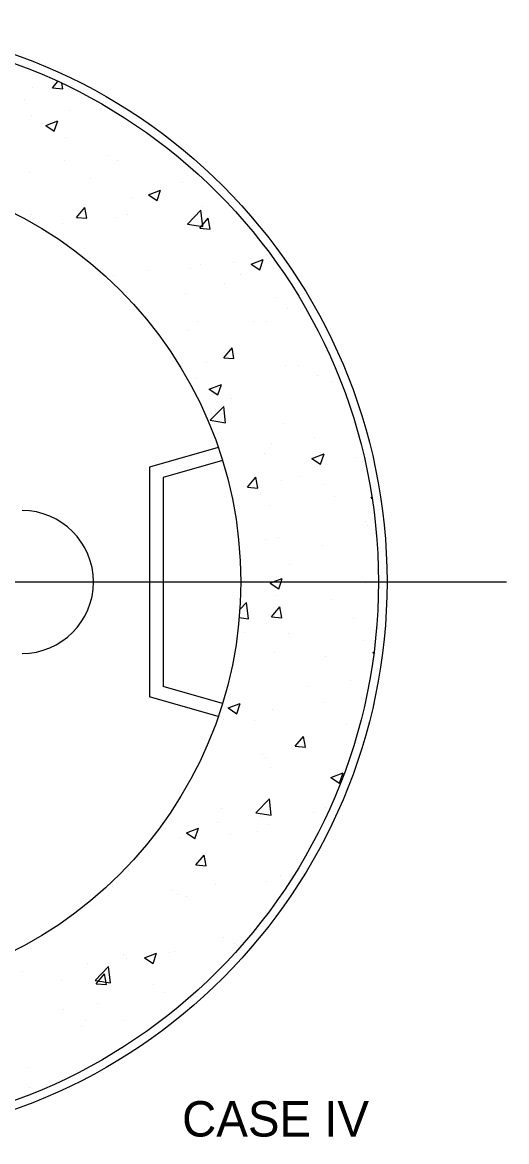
# Model space of a CAD drawing. Extents: x 6712067 to 6713867, y 1867712 to 1869162.
# Drawn here: x 6713358.3 to 6713440.3, y 1867927.4 to 1868116.9 of the extents above; entities that cross this region are included whole.
import ezdxf

# ---------------------------------------------------------------- set-up
doc = ezdxf.new("R2010")
doc.units = 0
doc.layers.add('Misc CnstDet(22)', color=7, linetype='Continuous')

msp = doc.modelspace()

# ---------------------------------------------------------------- linework, layer by layer
at = {"layer": 'Misc CnstDet(22)'}
for p, q in [((6713360.06, 1868105.89), (6713360.06, 1868105.89)), ((6713363.4, 1868105.8), (6713364.32, 1868106.89)), ((6713363.4, 1868105.8), (6713365.14, 1868105.65)), ((6713365.14, 1868105.64), (6713364.97, 1868106.58)), ((6713358.68, 1868103.8), (6713358.68, 1868103.8)), ((6713366.2, 1868101.98), (6713366.2, 1868101.98)), ((6713359.76, 1868101.15), (6713359.76, 1868101.15)), ((6713362.25, 1868099.43), (6713364.3, 1868100.22)), ((6713363.7, 1868098.45), (6713364.28, 1868100.21)), ((6713362.25, 1868099.43), (6713363.7, 1868098.45)), ((6713365.66, 1868097.41), (6713365.66, 1868097.41)), ((6713372.71, 1868094.39), (6713372.71, 1868094.39)), ((6713365.41, 1868093.43), (6713365.41, 1868093.43)), ((6713374.38, 1868093.51), (6713374.38, 1868093.51)), ((6713359.42, 1868091.45), (6713359.42, 1868091.45)), ((6713369.82, 1868090.42), (6713369.82, 1868090.42)), ((6713379.65, 1868087.7), (6713381.69, 1868088.48)), ((6713381.1, 1868086.71), (6713381.69, 1868088.48)), ((6713385.38, 1868089.75), (6713385.38, 1868089.75)), ((6713376.79, 1868087.21), (6713376.79, 1868087.21)), ((6713379.65, 1868087.7), (6713381.1, 1868086.71)), ((6713359.8, 1868084.29), (6713359.8, 1868084.29)), ((6713367.45, 1868083.87), (6713368.85, 1868085.54)), ((6713369.2, 1868083.72), (6713368.85, 1868085.54)), ((6713376.08, 1868084.35), (6713376.08, 1868084.35)), ((6713386.27, 1868082.74), (6713388.53, 1868085.11)), ((6713388.85, 1868082.33), (6713388.53, 1868085.11)), ((6713388.75, 1868085.67), (6713388.75, 1868085.67)), ((6713365.04, 1868082.89), (6713365.04, 1868082.89)), ((6713367.45, 1868083.87), (6713369.2, 1868083.72)), ((6713374.03, 1868083.8), (6713374.03, 1868083.8)), ((6713386.27, 1868082.74), (6713388.85, 1868082.34)), ((6713388.36, 1868082.04), (6713389.76, 1868083.72)), ((6713390.09, 1868081.88), (6713389.76, 1868083.72)), ((6713388.36, 1868082.04), (6713390.1, 1868081.89)), ((6713397.05, 1868075.96), (6713399.09, 1868076.74)), ((6713398.49, 1868074.98), (6713399.09, 1868076.74)), ((6713379.71, 1868074.86), (6713379.71, 1868074.86)), ((6713386.82, 1868075.27), (6713386.82, 1868075.27)), ((6713388.39, 1868075.96), (6713388.39, 1868075.96)), ((6713394.12, 1868076.24), (6713394.12, 1868076.24)), ((6713397.05, 1868075.96), (6713398.49, 1868074.98)), ((6713373.67, 1868074.1), (6713373.67, 1868074.1)), ((6713395.27, 1868074.2), (6713395.27, 1868074.2)), ((6713392.6, 1868072.74), (6713392.6, 1868072.74)), ((6713385.85, 1868070.95), (6713385.85, 1868070.95)), ((6713401.41, 1868070.29), (6713401.41, 1868070.29)), ((6713403.18, 1868068.44), (6713403.18, 1868068.44)), ((6713388.04, 1868066.26), (6713388.04, 1868066.26)), ((6713397.5, 1868066.18), (6713397.5, 1868066.18)), ((6713399.57, 1868066.33), (6713399.57, 1868066.33)), ((6713386.46, 1868064.74), (6713386.46, 1868064.74)), ((6713382.58, 1868063.42), (6713382.58, 1868063.42)), ((6713392.4, 1868060.11), (6713393.81, 1868061.79)), ((6713394.14, 1868059.96), (6713393.81, 1868061.79)), ((6713392.4, 1868060.11), (6713394.14, 1868059.96)), ((6713389.46, 1868059.39), (6713389.46, 1868059.39)), ((6713402.82, 1868058.75), (6713402.82, 1868058.75)), ((6713405.02, 1868058.73), (6713405.02, 1868058.73)), ((6713387.68, 1868056.55), (6713387.68, 1868056.55)), ((6713408.24, 1868057.12), (6713408.24, 1868057.12)), ((6713410.7, 1868056.13), (6713410.7, 1868056.13)), ((6713389.82, 1868054.7), (6713389.82, 1868054.7)), ((6713389.96, 1868054.82), (6713392, 1868055.6)), ((6713389.96, 1868054.82), (6713391.4, 1868053.85)), ((6713391.4, 1868053.85), (6713392, 1868055.6)), ((6713393.71, 1868053.21), (6713393.71, 1868053.21)), ((6713390.13, 1868049.52), (6713392.4, 1868051.88)), ((6713392.72, 1868049.12), (6713392.4, 1868051.88)), ((6713390.13, 1868049.52), (6713392.72, 1868049.12)), ((6713402.48, 1868049.04), (6713402.48, 1868049.04)), ((6713407.86, 1868046.58), (6713407.86, 1868046.58)), ((6713391.47, 1868044.93), (6713379.83, 1868041.6)), ((6713400.56, 1868045.62), (6713400.56, 1868045.62)), ((6713392.19, 1868042.71), (6713382.17, 1868039.85)), ((6713399.35, 1868043.84), (6713399.35, 1868043.84)), ((6713407.35, 1868043.08), (6713409.4, 1868043.87)), ((6713407.35, 1868043.08), (6713408.8, 1868042.11)), ((6713408.8, 1868042.11), (6713409.4, 1868043.86)), ((6713414.92, 1868043.17), (6713414.92, 1868043.17)), ((6713379.83, 1868041.6), (6713379.83, 1868002.69)), ((6713382.17, 1868039.85), (6713382.17, 1868004.45)), ((6713396.45, 1868038.19), (6713397.85, 1868039.87)), ((6713398.18, 1868038.03), (6713397.85, 1868039.87)), ((6713402.12, 1868039.34), (6713402.12, 1868039.34)), ((6713405.49, 1868039.93), (6713405.49, 1868039.93)), ((6713396.45, 1868038.19), (6713398.18, 1868038.04)), ((6713409.5, 1868038.73), (6713409.5, 1868038.73)), ((6713400.19, 1868035.08), (6713400.19, 1868035.08)), ((6713411.23, 1868036.54), (6713411.23, 1868036.54)), ((6713417.35, 1868036.36), (6713417.49, 1868036.53)), ((6713417.35, 1868036.36), (6713417.52, 1868036.35)), ((6713416.49, 1868032.34), (6713416.49, 1868032.34)), ((6713416.73, 1868031.69), (6713416.73, 1868031.69)), ((6713399.49, 1868029.41), (6713399.49, 1868029.41)), ((6713401.76, 1868029.63), (6713401.76, 1868029.63)), ((6713409.11, 1868028.36), (6713409.11, 1868028.36)), ((6713403.57, 1868025.04), (6713403.57, 1868025.04)), ((6713210.33, 1868022.15), (6713440.32, 1868022.15)), ((6713400.26, 1868021.95), (6713400.78, 1868022.15)), ((6713400.26, 1868021.95), (6713401.71, 1868020.97)), ((6713400.78, 1868022.15), (6713402.3, 1868022.73)), ((6713401.71, 1868020.97), (6713402.11, 1868022.15)), ((6713402.11, 1868022.15), (6713402.3, 1868022.73)), ((6713416.37, 1868021.98), (6713416.37, 1868021.98)), ((6713401.41, 1868019.92), (6713401.41, 1868019.92)), ((6713395.13, 1868017.48), (6713396.27, 1868018.66)), ((6713396.59, 1868015.89), (6713396.27, 1868018.66)), ((6713410.62, 1868019.22), (6713410.62, 1868019.22)), ((6713395.03, 1868016.14), (6713396.59, 1868015.89)), ((6713400.49, 1868016.26), (6713401.89, 1868017.94)), ((6713400.49, 1868016.26), (6713402.23, 1868016.11)), ((6713402.23, 1868016.11), (6713401.89, 1868017.94)), ((6713414.31, 1868015.96), (6713414.31, 1868015.96)), ((6713395.9, 1868013.54), (6713395.9, 1868013.54)), ((6713403.44, 1868013.46), (6713403.44, 1868013.46)), ((6713416.02, 1868012.28), (6713416.02, 1868012.28)), ((6713401.05, 1868010.23), (6713401.05, 1868010.23)), ((6713409.58, 1868009.55), (6713409.58, 1868009.55)), ((6713417.66, 1868010.21), (6713417.85, 1868010.28)), ((6713417.66, 1868010.21), (6713417.82, 1868010.1)), ((6713413.93, 1868005.43), (6713413.93, 1868005.43)), ((6713392.19, 1868001.58), (6713382.17, 1868004.45)), ((6713406.64, 1868004.46), (6713406.64, 1868004.46)), ((6713391.47, 1867999.37), (6713379.83, 1868002.69)), ((6713393.17, 1868000.82), (6713395.21, 1868001.6)), ((6713394.61, 1867999.83), (6713395.21, 1868001.6)), ((6713409.42, 1868001.83), (6713409.42, 1868001.83)), ((6713415.66, 1868002.57), (6713415.66, 1868002.57)), ((6713393.17, 1868000.82), (6713394.61, 1867999.83)), ((6713400.7, 1868000.52), (6713400.7, 1868000.52)), ((6713392.42, 1867998.91), (6713392.42, 1867998.91)), ((6713397.63, 1867998.65), (6713397.63, 1867998.65)), ((6713413.19, 1867997.99), (6713413.19, 1867997.99)), ((6713404.53, 1867994.34), (6713405.94, 1867996.02)), ((6713406.27, 1867994.18), (6713405.94, 1867996.01)), ((6713404.53, 1867994.34), (6713406.27, 1867994.18)), ((6713406.26, 1867993.93), (6713406.26, 1867993.93)), ((6713398.96, 1867992.98), (6713398.96, 1867992.98)), ((6713399.4, 1867992.51), (6713399.4, 1867992.51)), ((6713400.34, 1867990.82), (6713400.34, 1867990.82)), ((6713410.57, 1867989.08), (6713412.61, 1867989.86)), ((6713412.01, 1867988.1), (6713412.61, 1867989.86)), ((6713410.57, 1867989.08), (6713412.02, 1867988.1)), ((6713397.86, 1867983.09), (6713400.13, 1867985.45)), ((6713400.46, 1867982.67), (6713400.13, 1867985.45)), ((6713409.64, 1867983.89), (6713409.64, 1867983.89)), ((6713391.96, 1867983.75), (6713391.96, 1867983.75)), ((6713397.86, 1867983.09), (6713400.46, 1867982.68)), ((6713398.6, 1867982.44), (6713398.6, 1867982.44)), ((6713407.53, 1867983.1), (6713407.53, 1867983.1)), ((6713382.54, 1867980.5), (6713382.54, 1867980.5)), ((6713386.08, 1867979.68), (6713388.12, 1867980.46)), ((6713387.52, 1867978.69), (6713388.12, 1867980.46)), ((6713391.3, 1867981.48), (6713391.3, 1867981.48)), ((6713399.99, 1867981.11), (6713399.99, 1867981.11)), ((6713384.85, 1867978.93), (6713384.85, 1867978.93)), ((6713386.08, 1867979.68), (6713387.52, 1867978.7)), ((6713393.54, 1867979.39), (6713393.54, 1867979.39)), ((6713398.1, 1867979.84), (6713398.1, 1867979.84)), ((6713387.67, 1867974.25), (6713389.07, 1867975.91)), ((6713389.42, 1867974.09), (6713389.07, 1867975.91)), ((6713387.67, 1867974.25), (6713389.42, 1867974.09)), ((6713390.93, 1867970.94), (6713390.93, 1867970.94)), ((6713399.63, 1867971.41), (6713399.63, 1867971.41)), ((6713401.97, 1867972.39), (6713401.97, 1867972.39)), ((6713383.63, 1867969.98), (6713383.63, 1867969.98)), ((6713384.49, 1867969.22), (6713384.49, 1867969.22)), ((6713386.16, 1867968.94), (6713386.16, 1867968.94)), ((6713369.77, 1867967.36), (6713369.77, 1867967.36)), ((6713392.33, 1867961.99), (6713392.33, 1867961.99)), ((6713378.98, 1867958.54), (6713381.03, 1867959.32)), ((6713380.43, 1867957.55), (6713381.03, 1867959.32)), ((6713383.27, 1867959.44), (6713383.27, 1867959.44)), ((6713384.14, 1867959.52), (6713384.14, 1867959.52)), ((6713394.3, 1867960.9), (6713394.3, 1867960.9)), ((6713369.41, 1867957.65), (6713369.41, 1867957.65)), ((6713375.34, 1867959.08), (6713375.34, 1867959.08)), ((6713375.97, 1867958.48), (6713375.97, 1867958.48)), ((6713378.98, 1867958.54), (6713380.43, 1867957.56)), ((6713358.34, 1867956.16), (6713358.34, 1867956.16)), ((6713370.62, 1867954.68), (6713372.89, 1867957.06)), ((6713370.81, 1867954.14), (6713372.21, 1867955.82)), ((6713372.55, 1867953.99), (6713372.21, 1867955.82)), ((6713373.21, 1867954.28), (6713372.89, 1867957.05)), ((6713364.93, 1867954.7), (6713364.93, 1867954.7)), ((6713370.62, 1867954.68), (6713373.21, 1867954.28)), ((6713370.81, 1867954.14), (6713372.55, 1867953.99)), ((6713380.49, 1867954.04), (6713380.49, 1867954.04)), ((6713382.31, 1867952.67), (6713382.31, 1867952.67)), ((6713371.07, 1867950.78), (6713371.07, 1867950.78)), ((6713383.78, 1867949.82), (6713383.78, 1867949.82)), ((6713365.32, 1867949.76), (6713365.32, 1867949.76)), ((6713369.06, 1867947.96), (6713369.06, 1867947.96)), ((6713375.59, 1867947.95), (6713375.59, 1867947.95)), ((6713368.3, 1867946.98), (6713368.3, 1867946.98)), ((6713359.12, 1867939.89), (6713359.12, 1867939.89)), ((6713359.45, 1867936.64), (6713359.45, 1867936.64))]:
    msp.add_line(p, q, dxfattribs=at)
for radius in [94.73, 93.28, 69.96]:
    msp.add_circle((6713325.33, 1868022.15), radius, dxfattribs=at)
msp.add_arc((6713358.24, 1868022.15), 12.1, 270, 90, dxfattribs=at)

# ---------------------------------------------------------------- texts
msp.add_text('CASE IV', height=6, dxfattribs=at).set_placement((6713385.35, 1867928.27))

doc.saveas('drawing.dxf')
